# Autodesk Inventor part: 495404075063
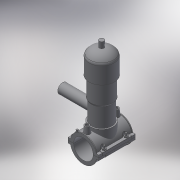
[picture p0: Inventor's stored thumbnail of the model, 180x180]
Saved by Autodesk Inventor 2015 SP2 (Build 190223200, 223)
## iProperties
Created: 2017-07
Part Number: 495404075063
Material: Generic
Description: PLASSON TAPPING VALVE 75-63
Document SubType Name: Modeling
Designer: KIM
Density: 1 g/cm^3
Appearance: Default
Author: KIM
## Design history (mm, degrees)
derived "495404-4954S4.ipt"
feature "Solid1::495404-4954S4.ipt"
feature "Solid2::495404-4954S4.ipt"
tag "TaggingFeature1"
body "Solid1"
body "Solid2"
other parameters: "d_" = 75, "B_" = 117, "H_" = 186, "L_" = 118, "d_t" = 6, "d_1" = 63, "H_1" = 51, "H_2" = 244, "d148" = 1.125, "d160" = 1.125, "d169" = 3, "d192" = 6.8, "d228" = 50.4, "d0" = 75, "d2" = 117, "d3" = 18.75, "d4" = 118, "d5" = 0, "d6" = 0.1, "d8" = 0, "d19" = 6, "d20" = 6, "d21" = 70.8, "d23" = 0, "d24" = 35.4, "d26" = 0, "d27" = 3, "d28" = 3, "d29" = 3, "d30" = 25, "d31" = 6, "d32" = 0, "d33" = 0, "d34" = 0.6, "d40" = 50.7, "d47" = 99.75, "d70" = 15, "d72" = 0, "d73" = 6, "d75" = 5, "d76" = 0, "d77" = 3.75, "d78" = 67.5, "d79" = 15, "d80" = 47.2, "d82" = 5 deg, "d84" = 4, "d85" = 14, "d86" = 0, "d87" = 3, "d88" = 0, "d89" = 1, "d90" = 1, "d91" = 94.4, "d92" = 0, "d93" = 0.5, "d94" = 39.47368, "d96" = 100.425, "d97" = 2.36, "d98" = 0, "d120" = 140 deg, "d121" = 24.228, "d122" = 20 deg, "d123" = 195, "d124" = 58.5, "d126" = 0, "d143" = 77.25, "d145" = 17.30769, "d149" = 1.125, "d150" = 19.03846, "d153" = 118, "d154" = 0, "d156" = 48.75, "d157" = 160 deg, "d159" = 4.5, "d161" = 1.125, "d162" = 70.8, "d163" = 0, "d164" = 37.5, "d167" = 7.5, "d168" = 47.56098, "d170" = 3, "d172" = 0, "d173" = 1, "d175" = 37.5, "d176" = 20 deg, "d177" = 5.25, "d178" = 22.5, "d180" = 0, "d183" = 9, "d184" = 4.2, "d185" = 38.35, "d186" = 38.35, "d187" = 48.75, "d188" = 6.75, "d189" = 5.25, "d190" = 0, "d191" = 73.125, "d193" = 6.8, "d194" = 2.95, "d195" = 90 deg, "d197" = 0, "d199" = 0, "d205" = 14.64, "d206" = 81.33333, "d207" = 244, "d208" = 224.48, "d209" = 207.4, "d210" = 200.08, "d211" = 146.4, "d212" = 85.4, "d213" = 65.88, "d214" = 73.2, "d216" = 19.52, "d217" = 70.76, "d218" = 80.52, "d220" = 75, "d222" = 0, "d223" = 97.5, "d224" = 186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
